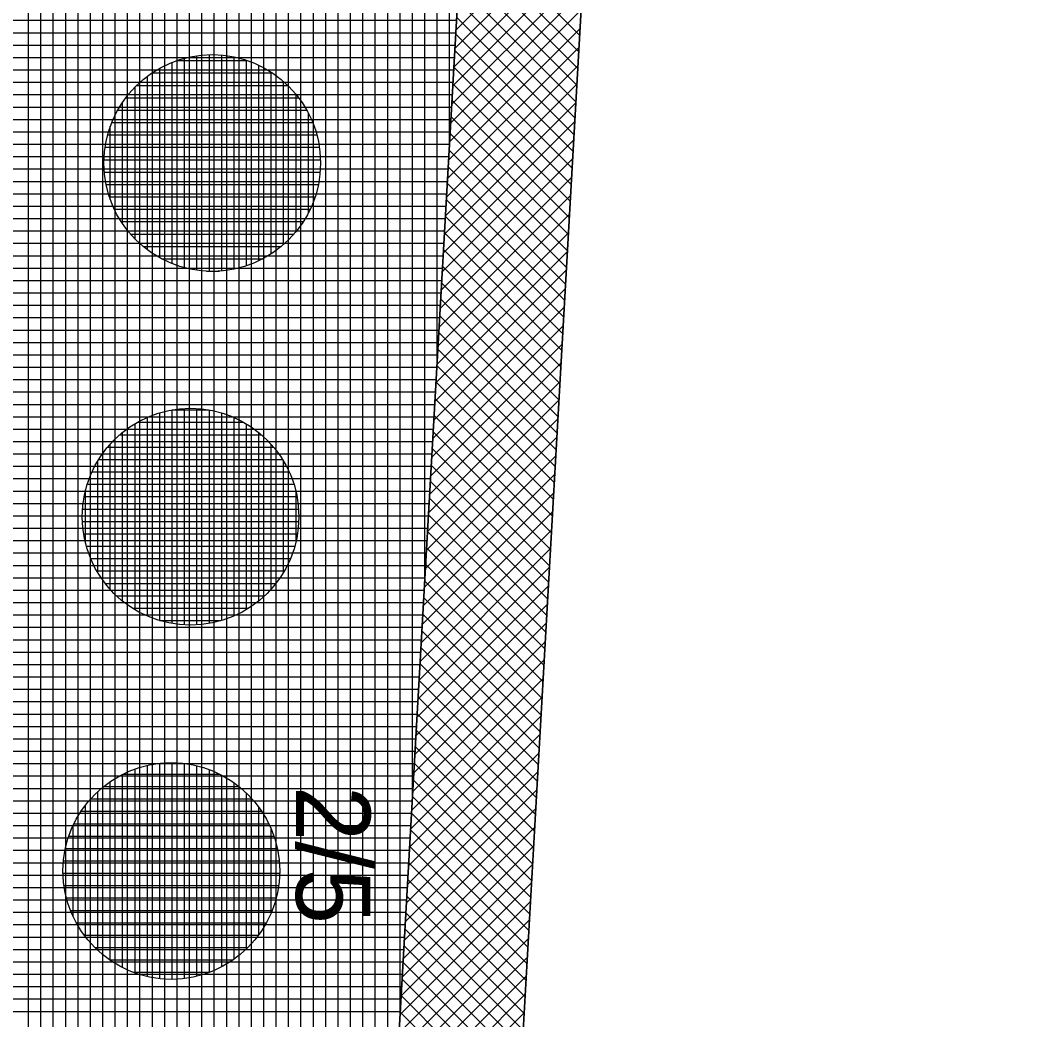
# Model space of a CAD drawing. Extents: x -565346 to -564154, y -1097386 to -1095620.
# Drawn here: x -564263.73 to -564247.53, y -1096626.73 to -1096610.59 of the extents above; entities that cross this region are included whole.
import ezdxf

# ---------------------------------------------------------------- set-up
doc = ezdxf.new("R2010")
doc.units = 0
for name, color, linetype in [('Vrstva 13', 7, 'Continuous'), ('Vrstva 40', 7, 'Continuous'), ('Vrstva 41', 7, 'Continuous'), ('Vrstva 42', 7, 'Continuous'), ('Vrstva 43', 7, 'Continuous'), ('Vrstva 44', 7, 'Continuous')]:
    doc.layers.add(name, color=color, linetype=linetype)

msp = doc.modelspace()

# ---------------------------------------------------------------- linework, layer by layer
at = {"layer": 'Vrstva 13'}
msp.add_line((-564252.76, -1096576.88), (-564261.08, -1096723.43), dxfattribs=at)
at = {"layer": 'Vrstva 41'}
msp.add_lwpolyline([(-564221.399, -1096446.296), (-564223.301, -1096445.676), (-564228.215, -1096460.758), (-564240.675, -1096505.018), (-564249.271, -1096529.938), (-564254.757, -1096576.767), (-564262.137, -1096706.758), (-564260.141, -1096706.872), (-564252.76, -1096576.88), (-564247.38, -1096530.59), (-564238.75, -1096505.56), (-564226.29, -1096461.3)], close=True, dxfattribs=at)
at = {"layer": 'Vrstva 42'}
for p, q in [((-564254.562, -1096608.623), (-564256.686, -1096610.746)), ((-564254.579, -1096608.922), (-564256.703, -1096611.046)), ((-564256.583, -1096608.938), (-564254.688, -1096610.834)), ((-564254.596, -1096609.222), (-564256.72, -1096611.346)), ((-564256.599, -1096609.206), (-564254.703, -1096611.101)), ((-564256.614, -1096609.473), (-564254.718, -1096611.369)), ((-564254.613, -1096609.522), (-564256.737, -1096611.646)), ((-564256.629, -1096609.741), (-564254.733, -1096611.637)), ((-564254.63, -1096609.822), (-564256.754, -1096611.946)), ((-564254.647, -1096610.122), (-564256.771, -1096612.246)), ((-564256.644, -1096610.009), (-564254.749, -1096611.904)), ((-564256.659, -1096610.276), (-564254.764, -1096612.172)), ((-564254.664, -1096610.422), (-564256.788, -1096612.546)), ((-564256.675, -1096610.544), (-564254.779, -1096612.44)), ((-564254.681, -1096610.722), (-564256.805, -1096612.846)), ((-564256.69, -1096610.812), (-564254.794, -1096612.707)), ((-564254.698, -1096611.022), (-564256.822, -1096613.145)), ((-564256.705, -1096611.079), (-564254.809, -1096612.975)), ((-564254.715, -1096611.321), (-564256.839, -1096613.445)), ((-564256.72, -1096611.347), (-564254.825, -1096613.243)), ((-564254.733, -1096611.621), (-564256.856, -1096613.745)), ((-564256.735, -1096611.615), (-564254.84, -1096613.51)), ((-564254.75, -1096611.921), (-564256.873, -1096614.045)), ((-564256.751, -1096611.882), (-564254.855, -1096613.778)), ((-564254.767, -1096612.221), (-564256.89, -1096614.345)), ((-564256.766, -1096612.15), (-564254.87, -1096614.046)), ((-564254.784, -1096612.521), (-564256.907, -1096614.645)), ((-564256.781, -1096612.418), (-564254.885, -1096614.313)), ((-564256.796, -1096612.685), (-564254.901, -1096614.581)), ((-564254.801, -1096612.821), (-564256.924, -1096614.945)), ((-564256.811, -1096612.953), (-564254.916, -1096614.848)), ((-564254.818, -1096613.121), (-564256.941, -1096615.244)), ((-564256.827, -1096613.22), (-564254.931, -1096615.116)), ((-564254.835, -1096613.42), (-564256.959, -1096615.544)), ((-564256.842, -1096613.488), (-564254.946, -1096615.384)), ((-564254.852, -1096613.72), (-564256.976, -1096615.844)), ((-564256.857, -1096613.756), (-564254.961, -1096615.651)), ((-564254.869, -1096614.02), (-564256.993, -1096616.144)), ((-564256.872, -1096614.023), (-564254.977, -1096615.919)), ((-564254.886, -1096614.32), (-564257.01, -1096616.444)), ((-564256.887, -1096614.291), (-564254.992, -1096616.187)), ((-564254.903, -1096614.62), (-564257.027, -1096616.744)), ((-564256.903, -1096614.559), (-564255.007, -1096616.454)), ((-564256.918, -1096614.826), (-564255.022, -1096616.722)), ((-564254.92, -1096614.92), (-564257.044, -1096617.044)), ((-564256.933, -1096615.094), (-564255.037, -1096616.99)), ((-564254.937, -1096615.22), (-564257.061, -1096617.344)), ((-564256.948, -1096615.362), (-564255.052, -1096617.257)), ((-564254.954, -1096615.52), (-564257.078, -1096617.643)), ((-564256.963, -1096615.629), (-564255.068, -1096617.525)), ((-564254.971, -1096615.819), (-564257.095, -1096617.943)), ((-564256.979, -1096615.897), (-564255.083, -1096617.793)), ((-564254.988, -1096616.119), (-564257.112, -1096618.243)), ((-564256.994, -1096616.165), (-564255.098, -1096618.06)), ((-564255.005, -1096616.419), (-564257.129, -1096618.543)), ((-564257.009, -1096616.432), (-564255.113, -1096618.328)), ((-564255.022, -1096616.719), (-564257.146, -1096618.843)), ((-564257.024, -1096616.7), (-564255.128, -1096618.596)), ((-564255.039, -1096617.019), (-564257.163, -1096619.143)), ((-564257.039, -1096616.968), (-564255.144, -1096618.863)), ((-564257.055, -1096617.235), (-564255.159, -1096619.131)), ((-564255.056, -1096617.319), (-564257.18, -1096619.443)), ((-564257.07, -1096617.503), (-564255.174, -1096619.398)), ((-564255.073, -1096617.619), (-564257.197, -1096619.742)), ((-564255.09, -1096617.918), (-564257.214, -1096620.042)), ((-564257.085, -1096617.77), (-564255.189, -1096619.666)), ((-564257.1, -1096618.038), (-564255.204, -1096619.934)), ((-564255.107, -1096618.218), (-564257.231, -1096620.342)), ((-564257.115, -1096618.306), (-564255.22, -1096620.201)), ((-564255.124, -1096618.518), (-564257.248, -1096620.642)), ((-564257.13, -1096618.573), (-564255.235, -1096620.469)), ((-564255.141, -1096618.818), (-564257.265, -1096620.942)), ((-564257.146, -1096618.841), (-564255.25, -1096620.737)), ((-564255.158, -1096619.118), (-564257.282, -1096621.242)), ((-564257.161, -1096619.109), (-564255.265, -1096621.004)), ((-564255.175, -1096619.418), (-564257.299, -1096621.542)), ((-564257.176, -1096619.376), (-564255.28, -1096621.272)), ((-564257.191, -1096619.644), (-564255.296, -1096621.54)), ((-564255.192, -1096619.718), (-564257.316, -1096621.842)), ((-564255.209, -1096620.018), (-564257.333, -1096622.141)), ((-564257.206, -1096619.912), (-564255.311, -1096621.807)), ((-564257.222, -1096620.179), (-564255.326, -1096622.075)), ((-564255.226, -1096620.317), (-564257.35, -1096622.441)), ((-564257.237, -1096620.447), (-564255.341, -1096622.343)), ((-564255.243, -1096620.617), (-564257.367, -1096622.741)), ((-564257.252, -1096620.715), (-564255.356, -1096622.61)), ((-564255.26, -1096620.917), (-564257.384, -1096623.041)), ((-564257.267, -1096620.982), (-564255.372, -1096622.878)), ((-564255.277, -1096621.217), (-564257.401, -1096623.341)), ((-564257.282, -1096621.25), (-564255.387, -1096623.145)), ((-564255.294, -1096621.517), (-564257.418, -1096623.641)), ((-564257.298, -1096621.518), (-564255.402, -1096623.413)), ((-564257.313, -1096621.785), (-564255.417, -1096623.681)), ((-564255.311, -1096621.817), (-564257.435, -1096623.941)), ((-564255.328, -1096622.117), (-564257.452, -1096624.24)), ((-564257.328, -1096622.053), (-564255.432, -1096623.948)), ((-564255.345, -1096622.417), (-564257.469, -1096624.54)), ((-564257.343, -1096622.32), (-564255.448, -1096624.216)), ((-564257.358, -1096622.588), (-564255.463, -1096624.484)), ((-564255.362, -1096622.716), (-564257.486, -1096624.84)), ((-564257.374, -1096622.856), (-564255.478, -1096624.751)), ((-564255.379, -1096623.016), (-564257.503, -1096625.14)), ((-564257.389, -1096623.123), (-564255.493, -1096625.019)), ((-564255.397, -1096623.316), (-564257.52, -1096625.44)), ((-564257.404, -1096623.391), (-564255.508, -1096625.287)), ((-564255.414, -1096623.616), (-564257.537, -1096625.74)), ((-564257.419, -1096623.659), (-564255.524, -1096625.554)), ((-564255.431, -1096623.916), (-564257.554, -1096626.04)), ((-564257.434, -1096623.926), (-564255.539, -1096625.822)), ((-564255.448, -1096624.216), (-564257.571, -1096626.34)), ((-564257.45, -1096624.194), (-564255.554, -1096626.09)), ((-564255.465, -1096624.516), (-564257.588, -1096626.639)), ((-564257.465, -1096624.462), (-564255.569, -1096626.357)), ((-564255.482, -1096624.815), (-564257.605, -1096626.939)), ((-564257.48, -1096624.729), (-564255.584, -1096626.625)), ((-564257.495, -1096624.997), (-564255.6, -1096626.893)), ((-564255.499, -1096625.115), (-564257.622, -1096627.239)), ((-564257.51, -1096625.265), (-564255.615, -1096627.16)), ((-564255.516, -1096625.415), (-564257.639, -1096627.539)), ((-564257.526, -1096625.532), (-564255.63, -1096627.428)), ((-564255.533, -1096625.715), (-564257.657, -1096627.839)), ((-564257.541, -1096625.8), (-564255.645, -1096627.695)), ((-564255.55, -1096626.015), (-564257.674, -1096628.139)), ((-564257.556, -1096626.068), (-564255.66, -1096627.963)), ((-564255.567, -1096626.315), (-564257.691, -1096628.439)), ((-564257.571, -1096626.335), (-564255.676, -1096628.231)), ((-564255.584, -1096626.615), (-564257.708, -1096628.738)), ((-564257.586, -1096626.603), (-564255.691, -1096628.498))]:
    msp.add_line(p, q, dxfattribs=at)
at = {"layer": 'Vrstva 43'}
for p, q in [((-564256.79, -1096612.576), (-564256.79, -1096529.275)), ((-564256.99, -1096616.099), (-564256.99, -1096530.995)), ((-564257.19, -1096619.622), (-564257.19, -1096532.716)), ((-564257.39, -1096623.145), (-564257.39, -1096534.437)), ((-564257.59, -1096626.667), (-564257.59, -1096536.157)), ((-564257.79, -1096630.19), (-564257.79, -1096537.878)), ((-564257.99, -1096633.713), (-564257.99, -1096539.599)), ((-564258.19, -1096637.236), (-564258.19, -1096541.32)), ((-564258.39, -1096640.759), (-564258.39, -1096543.04)), ((-564258.59, -1096644.281), (-564258.59, -1096544.761)), ((-564258.79, -1096647.804), (-564258.79, -1096546.482)), ((-564258.99, -1096651.327), (-564258.99, -1096548.203)), ((-564259.19, -1096654.85), (-564259.19, -1096549.923)), ((-564259.39, -1096658.372), (-564259.39, -1096551.644)), ((-564259.59, -1096661.895), (-564259.59, -1096553.365)), ((-564259.79, -1096665.418), (-564259.79, -1096555.085)), ((-564259.99, -1096668.941), (-564259.99, -1096556.806)), ((-564260.19, -1096672.464), (-564260.19, -1096558.527)), ((-564260.39, -1096675.986), (-564260.39, -1096560.248)), ((-564260.59, -1096679.509), (-564260.59, -1096561.968)), ((-564260.79, -1096683.032), (-564260.79, -1096563.689)), ((-564260.99, -1096686.555), (-564260.99, -1096565.41)), ((-564261.19, -1096690.078), (-564261.19, -1096567.13)), ((-564261.39, -1096693.6), (-564261.39, -1096568.851)), ((-564261.59, -1096697.123), (-564261.59, -1096570.572)), ((-564261.79, -1096700.646), (-564261.79, -1096572.293)), ((-564261.99, -1096704.169), (-564261.99, -1096574.013)), ((-564262.19, -1096726.788), (-564262.19, -1096575.734)), ((-564262.39, -1096726.776), (-564262.39, -1096578.915)), ((-564262.59, -1096726.765), (-564262.59, -1096582.438)), ((-564262.79, -1096726.753), (-564262.79, -1096585.961)), ((-564262.99, -1096726.742), (-564262.99, -1096589.485)), ((-564263.19, -1096726.731), (-564263.19, -1096593.008)), ((-564263.39, -1096728.822), (-564263.39, -1096596.531)), ((-564263.59, -1096732.346), (-564263.59, -1096600.055)), ((-564264.188, -1096610.59), (-564256.677, -1096610.59)), ((-564264.199, -1096610.79), (-564256.689, -1096610.79)), ((-564264.211, -1096610.99), (-564256.7, -1096610.99)), ((-564264.222, -1096611.19), (-564256.711, -1096611.19)), ((-564264.233, -1096611.39), (-564256.723, -1096611.39)), ((-564264.245, -1096611.59), (-564256.734, -1096611.59)), ((-564264.256, -1096611.79), (-564256.745, -1096611.79)), ((-564264.268, -1096611.99), (-564256.757, -1096611.99)), ((-564264.279, -1096612.19), (-564256.768, -1096612.19)), ((-564264.29, -1096612.39), (-564256.779, -1096612.39)), ((-564264.302, -1096612.59), (-564256.791, -1096612.59)), ((-564264.313, -1096612.79), (-564256.802, -1096612.79)), ((-564264.324, -1096612.99), (-564256.813, -1096612.99)), ((-564264.336, -1096613.19), (-564256.825, -1096613.19)), ((-564264.347, -1096613.39), (-564256.836, -1096613.39)), ((-564264.358, -1096613.59), (-564256.848, -1096613.59)), ((-564264.37, -1096613.79), (-564256.859, -1096613.79)), ((-564264.381, -1096613.99), (-564256.87, -1096613.99)), ((-564264.392, -1096614.19), (-564256.882, -1096614.19)), ((-564264.404, -1096614.39), (-564256.893, -1096614.39)), ((-564264.415, -1096614.59), (-564256.904, -1096614.59)), ((-564264.426, -1096614.79), (-564256.916, -1096614.79)), ((-564264.438, -1096614.99), (-564256.927, -1096614.99)), ((-564264.449, -1096615.19), (-564256.938, -1096615.19)), ((-564264.461, -1096615.39), (-564256.95, -1096615.39)), ((-564264.472, -1096615.59), (-564256.961, -1096615.59)), ((-564264.483, -1096615.79), (-564256.972, -1096615.79)), ((-564264.495, -1096615.99), (-564256.984, -1096615.99)), ((-564264.506, -1096616.19), (-564256.995, -1096616.19)), ((-564264.517, -1096616.39), (-564257.007, -1096616.39)), ((-564264.529, -1096616.59), (-564257.018, -1096616.59)), ((-564264.54, -1096616.79), (-564257.029, -1096616.79)), ((-564264.551, -1096616.99), (-564257.041, -1096616.99)), ((-564264.563, -1096617.19), (-564257.052, -1096617.19)), ((-564264.574, -1096617.39), (-564257.063, -1096617.39)), ((-564264.585, -1096617.59), (-564257.075, -1096617.59)), ((-564264.597, -1096617.79), (-564257.086, -1096617.79)), ((-564264.608, -1096617.99), (-564257.097, -1096617.99)), ((-564264.619, -1096618.19), (-564257.109, -1096618.19)), ((-564264.631, -1096618.39), (-564257.12, -1096618.39)), ((-564264.642, -1096618.59), (-564257.131, -1096618.59)), ((-564264.654, -1096618.79), (-564257.143, -1096618.79)), ((-564264.665, -1096618.99), (-564257.154, -1096618.99)), ((-564264.676, -1096619.19), (-564257.165, -1096619.19)), ((-564264.688, -1096619.39), (-564257.177, -1096619.39)), ((-564264.699, -1096619.59), (-564257.188, -1096619.59)), ((-564264.71, -1096619.79), (-564257.2, -1096619.79)), ((-564264.722, -1096619.99), (-564257.211, -1096619.99)), ((-564264.733, -1096620.19), (-564257.222, -1096620.19)), ((-564264.744, -1096620.39), (-564257.234, -1096620.39)), ((-564264.756, -1096620.59), (-564257.245, -1096620.59)), ((-564264.767, -1096620.79), (-564257.256, -1096620.79)), ((-564264.778, -1096620.99), (-564257.268, -1096620.99)), ((-564264.79, -1096621.19), (-564257.279, -1096621.19)), ((-564264.801, -1096621.39), (-564257.29, -1096621.39)), ((-564264.812, -1096621.59), (-564257.302, -1096621.59)), ((-564264.824, -1096621.79), (-564257.313, -1096621.79)), ((-564264.835, -1096621.99), (-564257.324, -1096621.99)), ((-564264.847, -1096622.19), (-564257.336, -1096622.19)), ((-564264.858, -1096622.39), (-564257.347, -1096622.39)), ((-564264.869, -1096622.59), (-564257.359, -1096622.59)), ((-564264.881, -1096622.79), (-564257.37, -1096622.79)), ((-564264.892, -1096622.99), (-564257.381, -1096622.99)), ((-564264.903, -1096623.19), (-564257.393, -1096623.19)), ((-564264.915, -1096623.39), (-564257.404, -1096623.39)), ((-564264.926, -1096623.59), (-564257.415, -1096623.59)), ((-564264.937, -1096623.79), (-564257.427, -1096623.79)), ((-564264.949, -1096623.99), (-564257.438, -1096623.99)), ((-564264.96, -1096624.19), (-564257.449, -1096624.19)), ((-564264.971, -1096624.39), (-564257.461, -1096624.39)), ((-564264.983, -1096624.59), (-564257.472, -1096624.59)), ((-564264.994, -1096624.79), (-564257.483, -1096624.79)), ((-564265.005, -1096624.99), (-564257.495, -1096624.99)), ((-564265.017, -1096625.19), (-564257.506, -1096625.19)), ((-564265.028, -1096625.39), (-564257.517, -1096625.39)), ((-564265.04, -1096625.59), (-564257.529, -1096625.59)), ((-564265.051, -1096625.79), (-564257.54, -1096625.79)), ((-564265.062, -1096625.99), (-564257.552, -1096625.99)), ((-564265.074, -1096626.19), (-564257.563, -1096626.19)), ((-564265.085, -1096626.39), (-564257.574, -1096626.39)), ((-564265.096, -1096626.59), (-564257.586, -1096626.59))]:
    msp.add_line(p, q, dxfattribs=at)
msp.add_lwpolyline([(-564261.274, -1096726.84), (-564260.141, -1096706.872), (-564262.137, -1096706.758), (-564254.757, -1096576.767), (-564249.271, -1096529.938), (-564240.675, -1096505.018), (-564228.215, -1096460.758), (-564223.301, -1096445.676), (-564221.399, -1096446.296), (-564218.92, -1096438.69), (-564229.82, -1096442.05), (-564230.6, -1096442.93), (-564256.683, -1096528.354), (-564262.228, -1096576.061), (-564269.623, -1096706.334), (-564272.07, -1096706.16), (-564273.28, -1096725.96)], dxfattribs=at)
at = {"layer": 'Vrstva 44'}
for p, q in [((-564261.27, -1096614.52), (-564261.27, -1096611.268)), ((-564261.19, -1096611.24), (-564260.058, -1096611.24)), ((-564261.07, -1096614.585), (-564261.07, -1096611.203)), ((-564260.87, -1096614.625), (-564260.87, -1096611.163)), ((-564260.67, -1096614.643), (-564260.67, -1096611.147)), ((-564260.47, -1096614.636), (-564260.47, -1096611.152)), ((-564260.27, -1096614.606), (-564260.27, -1096611.18)), ((-564260.07, -1096614.552), (-564260.07, -1096611.236)), ((-564261.47, -1096614.424), (-564261.47, -1096611.364)), ((-564259.87, -1096614.473), (-564259.87, -1096611.317)), ((-564259.67, -1096614.359), (-564259.67, -1096611.428)), ((-564261.67, -1096614.295), (-564261.67, -1096611.492)), ((-564261.595, -1096611.44), (-564259.651, -1096611.44)), ((-564259.47, -1096614.208), (-564259.47, -1096611.581)), ((-564261.87, -1096614.121), (-564261.87, -1096611.668)), ((-564261.843, -1096611.64), (-564259.404, -1096611.64)), ((-564262.07, -1096613.878), (-564262.07, -1096611.911)), ((-564262.02, -1096611.84), (-564259.23, -1096611.84)), ((-564259.27, -1096613.999), (-564259.27, -1096611.787)), ((-564262.15, -1096612.04), (-564259.097, -1096612.04)), ((-564262.245, -1096612.24), (-564259.003, -1096612.24)), ((-564259.07, -1096613.695), (-564259.07, -1096612.093)), ((-564262.27, -1096613.485), (-564262.27, -1096612.3)), ((-564262.313, -1096612.44), (-564258.936, -1096612.44)), ((-564262.355, -1096612.64), (-564258.894, -1096612.64)), ((-564262.372, -1096612.84), (-564258.875, -1096612.84)), ((-564262.366, -1096613.04), (-564258.881, -1096613.04)), ((-564262.338, -1096613.24), (-564258.911, -1096613.24)), ((-564262.286, -1096613.44), (-564258.964, -1096613.44)), ((-564262.206, -1096613.64), (-564259.042, -1096613.64)), ((-564262.094, -1096613.84), (-564259.154, -1096613.84)), ((-564261.946, -1096614.04), (-564259.304, -1096614.04)), ((-564261.74, -1096614.24), (-564259.509, -1096614.24)), ((-564261.443, -1096614.44), (-564259.808, -1096614.44)), ((-564260.717, -1096614.64), (-564260.506, -1096614.64)), ((-564261.47, -1096620.282), (-564261.47, -1096616.927)), ((-564261.272, -1096616.88), (-564260.685, -1096616.88)), ((-564261.27, -1096620.327), (-564261.27, -1096616.88)), ((-564261.07, -1096620.35), (-564261.07, -1096616.858)), ((-564260.87, -1096620.35), (-564260.87, -1096616.859)), ((-564260.67, -1096620.326), (-564260.67, -1096616.882)), ((-564260.47, -1096620.278), (-564260.47, -1096616.929)), ((-564261.87, -1096620.105), (-564261.87, -1096617.102)), ((-564261.83, -1096617.08), (-564260.117, -1096617.08)), ((-564261.67, -1096620.208), (-564261.67, -1096617)), ((-564260.27, -1096620.204), (-564260.27, -1096617.003)), ((-564260.07, -1096620.102), (-564260.07, -1096617.108)), ((-564262.07, -1096619.968), (-564262.07, -1096617.241)), ((-564259.87, -1096619.959), (-564259.87, -1096617.246)), ((-564262.27, -1096619.778), (-564262.27, -1096617.429)), ((-564262.116, -1096617.28), (-564259.832, -1096617.28)), ((-564262.313, -1096617.48), (-564259.633, -1096617.48)), ((-564259.67, -1096619.77), (-564259.67, -1096617.44)), ((-564262.47, -1096619.509), (-564262.47, -1096617.697)), ((-564262.459, -1096617.68), (-564259.49, -1096617.68)), ((-564259.47, -1096619.497), (-564259.47, -1096617.713)), ((-564262.567, -1096617.88), (-564259.382, -1096617.88)), ((-564262.642, -1096618.08), (-564259.305, -1096618.08)), ((-564262.67, -1096619.032), (-564262.67, -1096618.173)), ((-564259.27, -1096618.994), (-564259.27, -1096618.209)), ((-564262.692, -1096618.28), (-564259.256, -1096618.28)), ((-564262.719, -1096618.48), (-564259.231, -1096618.48)), ((-564262.722, -1096618.68), (-564259.227, -1096618.68)), ((-564262.701, -1096618.88), (-564259.247, -1096618.88)), ((-564262.656, -1096619.08), (-564259.291, -1096619.08)), ((-564262.587, -1096619.28), (-564259.362, -1096619.28)), ((-564262.489, -1096619.48), (-564259.461, -1096619.48)), ((-564262.352, -1096619.68), (-564259.596, -1096619.68)), ((-564262.171, -1096619.88), (-564259.778, -1096619.88)), ((-564261.913, -1096620.08), (-564260.036, -1096620.08)), ((-564261.477, -1096620.28), (-564260.477, -1096620.28)), ((-564261.47, -1096626.063), (-564261.47, -1096622.585)), ((-564261.27, -1096626.072), (-564261.27, -1096622.575)), ((-564261.07, -1096626.059), (-564261.07, -1096622.588)), ((-564262.07, -1096625.887), (-564262.07, -1096622.761)), ((-564262.069, -1096622.76), (-564260.503, -1096622.76)), ((-564261.87, -1096625.971), (-564261.87, -1096622.677)), ((-564261.67, -1096626.031), (-564261.67, -1096622.619)), ((-564260.87, -1096626.023), (-564260.87, -1096622.626)), ((-564260.67, -1096625.962), (-564260.67, -1096622.687)), ((-564260.47, -1096625.871), (-564260.47, -1096622.776)), ((-564262.27, -1096625.768), (-564262.27, -1096622.88)), ((-564260.27, -1096625.748), (-564260.27, -1096622.9)), ((-564262.47, -1096625.609), (-564262.47, -1096623.038)), ((-564262.378, -1096622.96), (-564260.189, -1096622.96)), ((-564260.07, -1096625.582), (-564260.07, -1096623.065)), ((-564262.67, -1096625.389), (-564262.67, -1096623.258)), ((-564262.591, -1096623.16), (-564259.98, -1096623.16)), ((-564262.742, -1096623.36), (-564259.825, -1096623.36)), ((-564259.87, -1096625.353), (-564259.87, -1096623.296)), ((-564262.87, -1096625.062), (-564262.87, -1096623.584)), ((-564262.857, -1096623.56), (-564259.712, -1096623.56)), ((-564259.67, -1096624.995), (-564259.67, -1096623.651)), ((-564262.94, -1096623.76), (-564259.629, -1096623.76)), ((-564262.994, -1096623.96), (-564259.573, -1096623.96)), ((-564263.025, -1096624.16), (-564259.544, -1096624.16)), ((-564263.032, -1096624.36), (-564259.537, -1096624.36)), ((-564263.018, -1096624.56), (-564259.552, -1096624.56)), ((-564262.978, -1096624.76), (-564259.59, -1096624.76)), ((-564262.912, -1096624.96), (-564259.655, -1096624.96)), ((-564262.82, -1096625.16), (-564259.749, -1096625.16)), ((-564262.693, -1096625.36), (-564259.875, -1096625.36)), ((-564262.521, -1096625.56), (-564260.048, -1096625.56)), ((-564262.281, -1096625.76), (-564260.287, -1096625.76)), ((-564261.902, -1096625.96), (-564260.665, -1096625.96))]:
    msp.add_line(p, q, dxfattribs=at)
for centre in [(-564260.624, -1096612.894), (-564260.974, -1096618.604), (-564261.284, -1096624.324)]:
    msp.add_circle(centre, 1.75, dxfattribs=at)

# ---------------------------------------------------------------- texts
at = {"layer": 'Vrstva 40'}
msp.add_text('2/5', height=1.2, rotation=270, dxfattribs=at).set_placement((-564259.27, -1096622.95))

doc.saveas('drawing.dxf')
